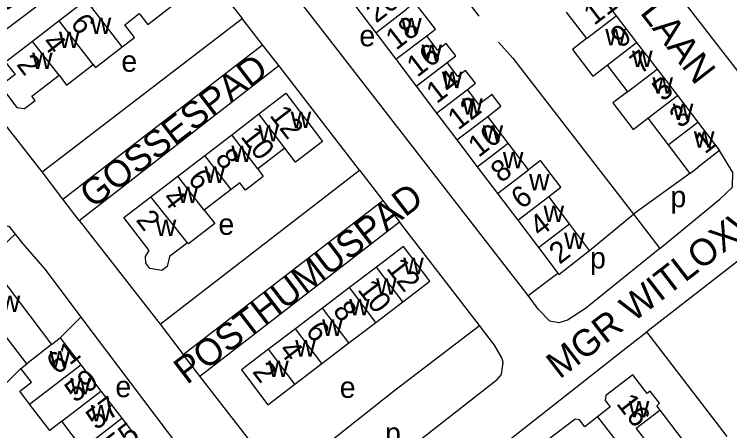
# Model space of a CAD drawing. Extents: x 158848 to 160613, y 385889 to 387762.
# Drawn here: x 159871.5 to 160005.9, y 386662.2 to 386740.3 of the extents above; entities that cross this region are included whole.
import ezdxf

# ---------------------------------------------------------------- set-up
doc = ezdxf.new("R2010")
doc.units = 0
for name, color, linetype in [('BLT_Basislijn', 7, 'Continuous'), ('BLT_Bebouwing', 7, 'Continuous'), ('BLT_Centroide', 7, 'Continuous'), ('BLT_Huisnummer', 7, 'Continuous'), ('BLT_Huisnummer_ tussenligend', 7, 'Continuous'), ('BLT_Onderverdeling_panden', 7, 'Continuous'), ('BLT_Straatnaam', 7, 'Continuous')]:
    doc.layers.add(name, color=color, linetype=linetype)

msp = doc.modelspace()

# ---------------------------------------------------------------- linework, layer by layer
at = {"layer": 'BLT_Basislijn'}
for p, q in [((159958.86, 386740.02), (159927.16, 386781.23)), ((159876.78, 386710.79), (159914.31, 386739.53)), ((159918.16, 386734.6), (159914.31, 386739.53)), ((159921.19, 386730.74), (159918.16, 386734.6)), ((159883.69, 386701.64), (159921.19, 386730.74)), ((159936.36, 386711.11), (159921.19, 386730.74)), ((159880.61, 386705.66), (159876.78, 386710.79)), ((159898.91, 386682.14), (159936.36, 386711.11)), ((159936.36, 386711.11), (159940.79, 386705.36)), ((159998.46, 386710.48), (159987.85, 386702.79)), ((159883.69, 386701.64), (159880.61, 386705.66)), ((159903.25, 386676.49), (159940.79, 386705.36)), ((159940.79, 386705.36), (159943.87, 386701.38)), ((159979.62, 386695.99), (159987.85, 386702.79)), ((159987.85, 386702.79), (159992.79, 386696.38)), ((159883.69, 386701.64), (159898.91, 386682.14)), ((159906.39, 386672.41), (159943.87, 386701.38)), ((159958.92, 386681.91), (159943.87, 386701.38)), ((159866.4, 386694.18), (159871.68, 386699.05)), ((159968.08, 386687.52), (159973.62, 386691.76)), ((159880.13, 386679.6), (159884.03, 386683.48)), ((159884.03, 386683.48), (159911, 386647.86)), ((159898.91, 386682.14), (159903.25, 386676.49)), ((160005.44, 386661.04), (159990.37, 386680.7)), ((159906.39, 386672.41), (159903.25, 386676.49)), ((159921.59, 386652.82), (159906.39, 386672.41)), ((159999.71, 386657.09), (159992.86, 386666.02))]:
    msp.add_line(p, q, dxfattribs=at)
for points in [[(159972.59, 386816.18), (159957.65, 386804.76), (159953.99, 386801.09), (159953.99, 386798.6), (160013.12, 386722.33), (160013.38, 386722.02)], [(159968.08, 386687.52), (159926.7, 386740.86), (159909.9, 386761.92), (159908.85, 386763.8), (159908.97, 386766.47), (159912.37, 386769.77), (159913.52, 386770.67)], [(159876.78, 386710.79), (159867.9, 386721.99), (159862.6, 386729.21), (159862.93, 386731.36), (159863.65, 386732.55), (159865.86, 386734.47), (159894.82, 386756.24), (159897.3, 386757.8), (159899.65, 386757.52), (159902.45, 386754.7), (159914.31, 386739.53)], [(159880.61, 386705.66), (159918.16, 386734.6)], [(159962.49, 386735.13), (159965.17, 386732.08), (159987.85, 386702.79)], [(160037.07, 386716.89), (160025.45, 386707.93), (159990.37, 386680.7)], [(159992.79, 386696.38), (160004.07, 386705.64), (160006.45, 386707.89), (160006.49, 386710.63), (160004.03, 386714.75)], [(159863.09, 386697.94), (159866.56, 386700.55), (159868.09, 386701.01), (159870.48, 386700.55), (159871.68, 386699.05)], [(159871.68, 386699.05), (159873.15, 386697.23), (159877.29, 386692.41), (159884.03, 386683.48)], [(159992.79, 386696.38), (159978.82, 386685.08), (159975.47, 386682.93), (159973.82, 386682.4), (159972.16, 386682.73), (159969.98, 386684.89), (159968.08, 386687.52)], [(159921.59, 386652.82), (159942.74, 386669.61), (159958.92, 386681.91)], [(159921.59, 386652.82), (159924.88, 386648.51), (159927.11, 386646.48), (159929.97, 386646.58), (159962.27, 386671.77), (159963.06, 386672.72), (159963.34, 386675), (159963.14, 386675.85), (159961.74, 386678.2), (159958.92, 386681.91)], [(159957.66, 386604.4), (159956.57, 386605.79), (159953.09, 386610.25), (159934.35, 386634.59), (159934.32, 386635.86), (159937.29, 386639.04), (159985.85, 386677.21), (159990.37, 386680.7)], [(159861.05, 386661.75), (159862.04, 386663.07), (159872.74, 386673.87)]]:
    msp.add_lwpolyline(points, dxfattribs=at)
at = {"layer": 'BLT_Bebouwing'}
for p, q in [((159980.8, 386745.04), (159984.63, 386740.05)), ((159885.02, 386743.01), (159879.97, 386739.13)), ((159935.62, 386741.9), (159939.43, 386736.87)), ((159975.23, 386740.77), (159979.05, 386735.78)), ((159984.63, 386740.05), (159988.45, 386735.06)), ((159879.97, 386739.13), (159874.92, 386735.25)), ((159939.43, 386736.87), (159943.18, 386731.91)), ((159988.45, 386735.06), (159992.28, 386730.07)), ((159943.18, 386731.91), (159947.01, 386726.86)), ((159982.88, 386730.8), (159986.71, 386725.81)), ((159992.28, 386730.07), (159996.11, 386725.09)), ((159947.01, 386726.86), (159950.84, 386721.81)), ((159996.11, 386725.09), (159999.93, 386720.1)), ((159912.39, 386717.74), (159917.45, 386721.63)), ((159950.84, 386721.81), (159954.67, 386716.76)), ((159964.33, 386716.13), (159960.5, 386721.17)), ((159990.53, 386720.82), (159994.36, 386715.83)), ((159999.93, 386720.1), (160004.03, 386714.75)), ((159907.33, 386713.85), (159912.39, 386717.74)), ((159954.67, 386716.76), (159958.5, 386711.71)), ((159968.1, 386711.17), (159964.33, 386716.13)), ((159994.36, 386715.83), (159998.46, 386710.48)), ((159922.33, 386715.2), (159917.3, 386711.34)), ((160004.03, 386714.75), (160000, 386711.66)), ((159902.26, 386709.96), (159907.33, 386713.85)), ((159958.5, 386711.71), (159962.29, 386706.71)), ((159998.46, 386710.48), (160000, 386711.66)), ((159897.2, 386706.07), (159902.26, 386709.96)), ((159912.24, 386707.45), (159907.18, 386703.56)), ((159962.29, 386706.71), (159966.1, 386701.68)), ((159975.83, 386700.99), (159971.92, 386706.14)), ((159966.1, 386701.68), (159969.98, 386696.55)), ((159979.62, 386695.99), (159975.83, 386700.99)), ((159969.98, 386696.55), (159973.62, 386691.76)), ((159866.4, 386694.18), (159878.54, 386678.37)), ((159939.55, 386692.88), (159934.48, 386689.02)), ((159934.48, 386689.02), (159929.41, 386685.16)), ((159939.46, 386682.49), (159944.53, 386686.35)), ((159929.41, 386685.16), (159924.34, 386681.3)), ((159873.85, 386674.72), (159867.35, 386683.18)), ((159934.39, 386678.63), (159939.46, 386682.49)), ((159924.34, 386681.3), (159919.27, 386677.44)), ((159878.54, 386678.37), (159880.13, 386679.6)), ((159880.13, 386679.6), (159884.01, 386674.54)), ((159929.32, 386674.77), (159934.39, 386678.63)), ((159872.74, 386673.87), (159873.85, 386674.72)), ((159884.01, 386674.54), (159887.79, 386669.61)), ((159924.25, 386670.9), (159929.32, 386674.77)), ((159887.79, 386669.61), (159891.71, 386664.5)), ((159891.71, 386664.5), (159895.45, 386659.62))]:
    msp.add_line(p, q, dxfattribs=at)
for points in [[(159894.99, 386740.49), (159896.58, 386738.43), (159901.62, 386742.31), (159900.04, 386744.37)], [(159949, 386736.32), (159950.65, 386737.53), (159946.8, 386742.56), (159945.21, 386741.31)], [(159891.78, 386734.22), (159894.11, 386736.01), (159892.27, 386738.4), (159894.99, 386740.49)], [(159952.83, 386731.27), (159954.48, 386732.55), (159952.69, 386734.89), (159951.06, 386733.64), (159949, 386736.32)], [(159979.05, 386735.78), (159976.4, 386733.75), (159980.22, 386728.76), (159982.88, 386730.8)], [(159874.92, 386735.25), (159869.87, 386731.37), (159871.67, 386729.03), (159868.9, 386726.9), (159872.02, 386722.83), (159873.43, 386722.65), (159875.41, 386724.17), (159874.8, 386724.96), (159879.93, 386728.9)], [(159886.35, 386730.92), (159886.77, 386730.36), (159891.78, 386734.22)], [(159879.93, 386728.9), (159881.34, 386727.07), (159886.35, 386730.92)], [(159956.67, 386726.22), (159958.17, 386727.4), (159956.31, 386729.82), (159954.83, 386728.68), (159952.83, 386731.27)], [(159917.45, 386721.63), (159922.51, 386725.51), (159929.44, 386716.49), (159924.35, 386712.57), (159922.33, 386715.2)], [(159960.5, 386721.17), (159962.96, 386723.12), (159961.28, 386725.3), (159958.82, 386723.41), (159956.67, 386726.22)], [(159986.71, 386725.81), (159983.99, 386723.72), (159987.81, 386718.73), (159990.53, 386720.82)], [(159971.92, 386706.14), (159974.19, 386707.87), (159970.38, 386712.89), (159968.1, 386711.17)], [(159917.3, 386711.34), (159918.3, 386709.89), (159914.95, 386707.31), (159913.88, 386708.71), (159912.24, 386707.45)], [(159904.06, 386697.45), (159900.69, 386694.86), (159900.24, 386693.01), (159899.27, 386692.26), (159896.97, 386692.62), (159896.23, 386693.59), (159896.15, 386694.84), (159896.88, 386696.01), (159892.13, 386702.18), (159897.2, 386706.07)], [(159907.18, 386703.56), (159909.18, 386701.04), (159904.22, 386697.24), (159904.06, 386697.45)], [(159944.53, 386686.35), (159949.6, 386690.21), (159944.62, 386696.74), (159939.55, 386692.88)], [(159973.62, 386691.76), (159973.81, 386691.5), (159979.62, 386695.99)], [(159919.27, 386677.44), (159914.2, 386673.58), (159919.18, 386667.04), (159924.25, 386670.9)], [(159874.39, 386667.15), (159872.54, 386669.57), (159874.75, 386671.26), (159872.74, 386673.87)], [(159992.86, 386666.02), (159992.22, 386666.84), (159992.75, 386667.35), (159991.01, 386669.61), (159990.42, 386669.15), (159987.73, 386672.67), (159982.63, 386668.75), (159982.56, 386667.81), (159983.48, 386666.62), (159981.09, 386664.77)], [(159880.42, 386663.94), (159878.17, 386662.22), (159874.39, 386667.15)], [(159992.86, 386666.02), (159988.38, 386662.59), (159991.78, 386658.14)], [(159981.09, 386664.77), (159978.7, 386662.91), (159977.74, 386664.17), (159976.87, 386664.31), (159971.94, 386660.54)], [(159884.34, 386658.84), (159880.42, 386663.94)]]:
    msp.add_lwpolyline(points, dxfattribs=at)
at = {"layer": 'BLT_Onderverdeling_panden'}
for p, q in [((159891.78, 386734.22), (159885.02, 386743.01)), ((159939.43, 386736.87), (159945.21, 386741.31)), ((159979.05, 386735.78), (159984.63, 386740.05)), ((159886.35, 386730.92), (159879.97, 386739.13)), ((159943.18, 386731.91), (159949, 386736.32)), ((159879.93, 386728.9), (159874.92, 386735.25)), ((159982.88, 386730.8), (159988.45, 386735.06)), ((159947.01, 386726.86), (159952.83, 386731.27)), ((159986.71, 386725.81), (159992.28, 386730.07)), ((159950.84, 386721.81), (159956.67, 386726.22)), ((159990.53, 386720.82), (159996.11, 386725.09)), ((159922.33, 386715.2), (159917.45, 386721.63)), ((159954.67, 386716.76), (159960.5, 386721.17)), ((159994.36, 386715.83), (159999.93, 386720.1)), ((159917.3, 386711.34), (159912.39, 386717.74)), ((159958.5, 386711.71), (159964.33, 386716.13)), ((159912.24, 386707.45), (159907.33, 386713.85)), ((159962.29, 386706.71), (159968.1, 386711.17)), ((159907.18, 386703.56), (159902.26, 386709.96)), ((159904.06, 386697.45), (159897.2, 386706.07)), ((159966.1, 386701.68), (159971.92, 386706.14)), ((159969.98, 386696.55), (159975.83, 386700.99)), ((159944.53, 386686.35), (159939.55, 386692.88)), ((159939.46, 386682.49), (159934.48, 386689.02)), ((159934.39, 386678.63), (159929.41, 386685.16)), ((159929.32, 386674.77), (159924.34, 386681.3)), ((159878.54, 386678.37), (159873.85, 386674.72)), ((159924.25, 386670.9), (159919.27, 386677.44)), ((159874.39, 386667.15), (159884.01, 386674.54)), ((159880.42, 386663.94), (159887.79, 386669.61)), ((159981.09, 386664.77), (159988.3, 386655.47)), ((159884.34, 386658.84), (159891.71, 386664.5))]:
    msp.add_line(p, q, dxfattribs=at)

# ---------------------------------------------------------------- texts
at = {"layer": 'BLT_Centroide'}
for s, p in [('w', (159885.88, 386736.67)), ('w', (159944.2, 386736.59)), ('e', (159936.35, 386734.34)), ('w', (159982.56, 386734.5)), ('w', (159879.91, 386734)), ('w', (159948.01, 386731.59)), ('w', (159874.86, 386730.09)), ('w', (159987.58, 386730.44)), ('e', (159891.63, 386729.56)), ('w', (159951.84, 386726.53)), ('w', (159991.41, 386725.44)), ('w', (159955.66, 386721.5)), ('w', (159995.23, 386720.47)), ('w', (159923.45, 386719.02)), ('w', (159917.36, 386716.47)), ('w', (159959.5, 386716.44)), ('w', (159999.2, 386715.28)), ('w', (159912.31, 386712.59)), ('w', (159963.31, 386711.41)), ('w', (159907.25, 386708.7)), ('w', (159968.23, 386707.28)), ('w', (159902.19, 386704.89)), ('p', (159994.8, 386704.12)), ('w', (159970.95, 386701.34)), ('w', (159898.09, 386698.7)), ('e', (159909.87, 386698.94)), ('w', (159974.83, 386696.25)), ('p', (159979.69, 386692.62)), ('w', (159944.58, 386691.55)), ('w', (159939.5, 386687.69)), ('w', (159868.78, 386684.47)), ('w', (159934.44, 386683.83)), ('w', (159929.36, 386679.97)), ('w', (159924.3, 386676.09)), ('w', (159878.14, 386674.03)), ('w', (159919.23, 386672.25)), ('w', (159882.03, 386668.97)), ('e', (159890.51, 386668.45)), ('e', (159932.66, 386668.32)), ('w', (159986.97, 386664.64)), ('w', (159885.88, 386663.94)), ('p', (159941.18, 386659.71))]:
    msp.add_text(s, height=4, dxfattribs=at).set_placement(p)
at = {"layer": 'BLT_Huisnummer'}
for s, rotation, p in [('6', 307.5578, (159881.92, 386738.57)), ('18', 37.6471, (159943.26, 386733.48)), ('9', 37.4854, (159985.49, 386733.86)), ('2', 307.5578, (159871.8, 386730.91)), ('14', 37.6471, (159950.89, 386723.45)), ('5', 37.4854, (159993.32, 386723.86)), ('12', 307.5578, (159919.36, 386721.33)), ('10', 37.6471, (159958.74, 386713.35)), ('1', 37.4854, (160001.26, 386713.99)), ('6', 307.5578, (159903.98, 386709.39)), ('6', 37.6471, (159966.82, 386703.61)), ('2', 307.5578, (159894.24, 386701.71)), ('2', 37.6471, (159973.97, 386693.29)), ('12', 307.5578, (159941.29, 386692.64)), ('6', 307.5578, (159926.1, 386680.82)), ('61', 37.4945, (159879.56, 386672.54)), ('2', 307.5578, (159916.11, 386673.21)), ('57', 37.4945, (159886.94, 386662.16)), ('16', 307.6026, (159984.51, 386667.21))]:
    msp.add_text(s, height=4, rotation=rotation, dxfattribs=at).set_placement(p)
at = {"layer": 'BLT_Huisnummer_ tussenligend'}
for s, rotation, p in [('20', 37.6471, (159939.5, 386738.58)), ('11', 37.4854, (159980.45, 386738.15)), ('4', 307.5578, (159876.58, 386734.92)), ('16', 37.6471, (159947.21, 386728.4)), ('7', 37.4854, (159989.15, 386728.97)), ('12', 37.6471, (159954.91, 386718.47)), ('3', 37.4854, (159996.59, 386718.83)), ('10', 307.5578, (159913.91, 386717.35)), ('8', 307.5578, (159909.1, 386713.23)), ('8', 37.6471, (159962.99, 386708.57)), ('4', 307.5578, (159899.18, 386705.72)), ('4', 37.6471, (159970.28, 386698.4)), ('10', 307.5578, (159935.87, 386688.61)), ('8', 307.5578, (159931.22, 386684.65)), ('4', 307.5578, (159921.06, 386677.22)), ('59', 37.4945, (159882.95, 386667.28)), ('55', 37.4945, (159890.61, 386657.25))]:
    msp.add_text(s, height=4, rotation=rotation, dxfattribs=at).set_placement(p)
at = {"layer": 'BLT_Straatnaam'}
for s, rotation, p in [('JAN BOLLANDLAAN', 307.816, (159960.93, 386776.74)), ('SALLUSTIUSLAAN', 37.4429, (159856.1, 386730.3)), ('GOSSESPAD', 37.5, (159886.28, 386703.76)), ('MGR WITLOXWEG', 37.6708, (159973.98, 386671.74)), ('POSTHUMUSPAD', 37.5, (159903.97, 386670.71))]:
    msp.add_text(s, height=5, rotation=rotation, dxfattribs=at).set_placement(p)

doc.saveas('drawing.dxf')
